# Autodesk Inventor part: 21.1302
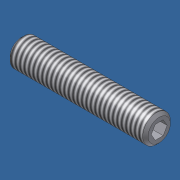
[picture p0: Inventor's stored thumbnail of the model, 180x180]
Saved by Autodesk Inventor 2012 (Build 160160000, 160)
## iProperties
Created: 2006-02
Part Number: 21.1302
Material: Steel, Mild
Description: M5x16 Set Screw Flat Point DIN 913 Zinc Plated
Document SubType Name: Modeling
Standard: DIN 913
Designer: Andy Moles
Standards Organization: DIN
Language: en-US
Size Designation: M5 x 25
Categories: <MemberInstance><Categories><Category DisplayName="Fasteners" InternalName="e4da775c-781d-43d5-af7c-5136215cf5a6" Mnemonic="FSTN"><Category DisplayName="Bolts"
Density: 7.86 g/cm^3
Mass: 2.29997 g
Surface Area: 3.08393 cm^2
Volume: 0.292617 cm^3
Vendor: S
Author: Andy Moles
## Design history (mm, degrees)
revolve "Body" stored, may be unused: angle "d6" = 90 deg
sketch "Sketch2"
  geometry: L1 (-0.722, 1.25)-(0.722, 1.25); L2 (0.722, 1.25)-(1.443, 0); L3 (1.443, 0)-(0.722, -1.25); L4 (0.722, -1.25)-(-0.722, -1.25); L5 (-0.722, -1.25)-(-1.443, 0); L6 (-1.443, 0)-(-0.722, 1.25); 3 further points
  constraints: 12 end point, 1 coincident, 1 horizontal, 13 other
extrude "Slot" join sketch "Sketch2" taper "d7" = 0 deg; stored distance "d21" = 10
workaxis "Work Axis1"
workplane "Work Plane1"
body "Solid1"
feature "Thread" dims "d8" = 16 (= NLG), "d9" = 0
chamfer "Chamfer1" distance "d10" = 0.49076 (= -0.5 x GD1 + 0.5 x NND); stored, may be unused: angle "d11" = 45 deg (= FAWI), second distance "d34" = 0.49076 (= -0.5 x GD1 + 0.5 x NND)
chamfer "Chamfer2" distance "d12" = 0.49076 (= -0.5 x GD1 + 0.5 x NND); stored, may be unused: angle "d13" = 45 deg (= FAWI), second distance "d35" = 0.49076 (= -0.5 x GD1 + 0.5 x NND)
sketch "Sketch1"
  geometry: L1 (0, 0)-(12.167, 0); L2 (16, 1.443)-(16, 2.5); L3 (16, 2.5)-(0, 2.5); L4 (16, 1.443)-(13, 1.443); L5 (13, 1.443)-(12.167, 0); L6 (0, -0.25)-(0, 3.25) reference; L7 (0, 2.5)-(0, 0)
  constraints: 13 end point, 3 parallel, 1 collinear, 1 perpendicular, 1 point on line
  dimensions: "d0" = 3 distance of L2.start L4.end (= INTI); "d1" = 60 deg angle of L5 L1; "d2" = 5 diameter of L3 L1 (= NND); "d3" = 2.88675 diameter of L4 L1 (= 1.1547 x SW); "d5" = 16 distance from line of L2 L3.end (= NLG)
other parameters: "NND" = 5 [user parameter; used in 5 equation terms], "NLG" = 16 [user parameter; used in 2 equation terms], "INTI" = 3 [user parameter; used in 1 equation term], "FAWI" = 45 deg [user parameter; used in 2 equation terms], "SW" = 2.5 [user parameter; used in 2 equation terms], "GD1" = 4.01848 (= THREADDIA - 1.2269 x PTC) [user parameter; used in 4 equation terms], "d4" = 0, "SPD" = 3.5 [user parameter], "d33" = 0, "d36" = 0, "GUL" = 0.49076 (= 0.61345 x PTC) [user parameter], "TPU" = 12.5 (computed from PTC) [user parameter], "TOA" = 30 deg [user parameter], "THREADDIA" = 5 [user parameter; used in 1 equation term], "PTC" = 0.8 [user parameter; used in 4 equation terms], "FAWI1" = 45 deg [user parameter], "GAL" = 0.49076 (= 0.61345 x PTC) [user parameter], "E0" = 2.8875 (= 1.155 x SW) [user parameter]
